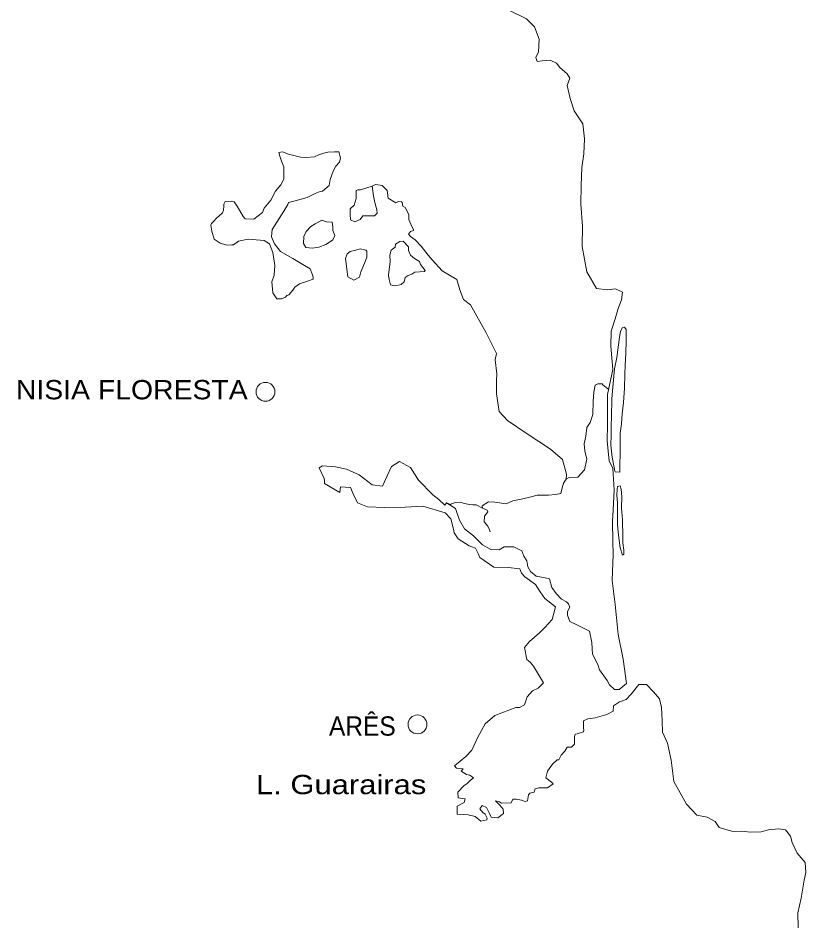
# Model space of a CAD drawing. Extents: x 47169 to 972804, y 7447977 to 9608469.
# Drawn here: x 910858 to 938638, y 9306596 to 9338655 of the extents above; entities that cross this region are included whole.
import ezdxf

# ---------------------------------------------------------------- set-up
doc = ezdxf.new("R2010")
doc.units = 0
doc.header["$LTSCALE"] = 270
doc.layers.add('1', color=7, linetype='Continuous', lineweight=13)
doc.layers.add('2', color=7, linetype='Continuous', lineweight=13)
doc.layers.add('3', color=7, linetype='Continuous')

msp = doc.modelspace()

# ---------------------------------------------------------------- linework, layer by layer
at = {"layer": '1'}
for points in [[(930542.9, 9317264.4), (931011.4, 9317032.8), (931085, 9316622.2), (931096.7, 9316405), (931118.5, 9316210.9), (931296.7, 9315855.1), (931357.4, 9315668.5), (931631.9, 9315287.5), (931709.5, 9315132.9), (931890.1, 9314969.8), (932050.9, 9314967.5), (932317.5, 9315181.7), (932195.2, 9316035.7), (932017.5, 9316906.8), (931914.3, 9317970.2), (931807.4, 9318816.4), (931838.6, 9319741.4), (931829.6, 9320191.3), (931824.9, 9320908.2), (931846.6, 9321301.4), (931873.9, 9322009.2), (931830.6, 9322766.3), (931698.4, 9323041), (931636.8, 9323726.2), (931646.7, 9324321.1), (931642, 9325053.6), (931647.7, 9325374.8), (931837, 9326257.7), (931762, 9327079.3), (931770.3, 9327609.9), (931913.1, 9328042.2), (932015.6, 9328410.4), (932132.1, 9328715.4), (932176.2, 9328987.6), (931930.8, 9329103.5), (931642.1, 9329067.9), (931258.6, 9329112.8), (930915.7, 9329704.7), (930753.5, 9330600), (930756.4, 9331315.8), (930704.3, 9332097.3), (930714.5, 9332748.7), (930733.5, 9333383.5), (930804.6, 9333873.8), (930837.2, 9334395.5), (930773.3, 9334927.8), (930468.2, 9335389.7), (930330.4, 9335826.2), (930226, 9336277.8), (930309.9, 9336534.3), (930216.7, 9336689), (929964.3, 9336916.8), (929845.6, 9337071.7), (929615.5, 9337171.9), (929334.7, 9337150.6), (929158.2, 9337120.8), (929120.3, 9337266.2), (929121.7, 9337298.4), (929203.7, 9337450.7), (929234.8, 9337916.9), (929073.6, 9338344.6), (928781.6, 9338630.3), (928138.2, 9338945.1)], [(927230.2, 9321372.5), (927223, 9321452.3), (927450.2, 9321594.7), (927674.2, 9321583.1), (928072.9, 9321513.8), (928306.7, 9321630.7), (928659.8, 9321691.3), (928900.9, 9321751.6), (929158.7, 9321828.4), (929558, 9321823.3), (929814.3, 9321843.6), (929999.8, 9321882.1), (930042.3, 9322082.4), (930085.6, 9322250.5), (930183.1, 9322386.1), (930202.2, 9322570.9), (930058.3, 9323079.5), (929631.8, 9323447.1), (928808.3, 9323989.3), (928119.7, 9324465.1), (927828, 9324775.2), (927726, 9325395.3), (927732.6, 9325861.7), (927736.6, 9326103.2), (927680.2, 9326594.5), (927731.8, 9326827.9), (927367.6, 9327548.4), (926814.6, 9328545.1), (926561.9, 9328734.1), (926431.2, 9329065.2), (926324, 9329437.2), (925817.1, 9329741), (925454.9, 9330132.5), (925321.9, 9330295.2), (925070.1, 9330611.6), (924857.6, 9330831.4), (924699.8, 9330946.6), (924620.6, 9331035.8), (924694.4, 9331131.7), (924798.9, 9331162), (924799.1, 9331194.1), (924744.5, 9331307.5), (924636.4, 9331550.9), (924631, 9331728.2), (924507.3, 9331970.6), (924427.9, 9332027.7), (924397.7, 9332148.6), (924374.6, 9332173.2), (924270.4, 9332182.8), (924181.3, 9332135.8), (923911.9, 9332308.3), (923868.3, 9332574.5), (923695.4, 9332754.1), (923623.3, 9332762.3), (923463.8, 9332781.2), (923342.5, 9332726.6), (923393.3, 9332387.2), (923437.2, 9332154.3), (923505.2, 9331895.6), (923519.9, 9331774.8), (923430.5, 9331679), (923149.9, 9331675.5), (923013.5, 9331685.3), (922916.1, 9331549.7), (922730.2, 9331463.5), (922579.9, 9331537.6), (922566.8, 9331722.8), (922561.6, 9331924.4), (922707.8, 9332058.6), (922774.9, 9332291.9), (922778.4, 9332476.9), (922779.1, 9332573.2), (922835.8, 9332596.1), (922932.3, 9332603.2), (923342.5, 9332726.6)], [(930183.1, 9322386.1), (930296.7, 9322448.4), (930592.9, 9322460.6), (930828.8, 9322723.7), (930914.7, 9323099.8), (930839.2, 9323390.7), (930819.9, 9323632.4), (930879.5, 9323905.6), (930908.3, 9324210.1), (931031.7, 9324394.3), (931123.5, 9324673.9), (931139.1, 9325140.3), (931160.3, 9325461.5), (931212, 9325710.4), (931301, 9325749.6), (931453, 9325755.2), (931477.1, 9325722.9), (931650.2, 9325576.5), (931686.4, 9325555.6)], [(926814.6, 9311772.7), (926911.7, 9311851.8), (926784.9, 9311950.2), (926665.2, 9311967.7), (926483.2, 9312090.9), (926548.1, 9312170.2), (926316.5, 9312189.6), (926246.2, 9312279.9), (926643.3, 9312603.8), (926854.5, 9312826.1), (927070.8, 9313289.9), (927325.9, 9313761.1), (927675.1, 9314054.4), (928415.7, 9314333.8), (928535.5, 9314339.6), (928721.3, 9314433.5), (928805.4, 9314706.5), (928993.2, 9314921.2), (929202.4, 9315015), (929381.2, 9315205.4), (929038.5, 9315797.3), (928920.8, 9315935.6), (928793.9, 9316025.1), (928720.5, 9316453.4), (928892.8, 9316659.3), (929241.1, 9316969.2), (929436.5, 9317151.7), (929689.1, 9317436.8), (929807.8, 9317885.8), (929436.2, 9318181.1), (929263.8, 9318416.1), (929100.4, 9318676.6), (928728.6, 9318938.5), (928610.9, 9319076.8), (928556.5, 9319222.3), (928141, 9319268.5), (927637.6, 9319283.2), (927138.9, 9319628.1), (927076.6, 9319765.9), (926991.5, 9319951.6), (926769.2, 9320042.9), (926372.8, 9320281.8), (926232.4, 9320493.3), (926210, 9320622), (926119.5, 9320992.7), (925922.5, 9321196.9), (925126.8, 9321433), (924510, 9321400.9), (923773.5, 9321386.2), (923173.8, 9321410.4), (922831, 9321560.2), (922668.1, 9321876), (922584.2, 9322094.9), (922231.8, 9322122.9), (922197.1, 9321922.6), (921665.9, 9322235.4), (921660.1, 9322356.2), (921645, 9322412.9), (921474.6, 9322785.2), (921587.2, 9322864.2), (922051.6, 9322825.4), (922442.4, 9322739.6), (922886.8, 9322540.3), (923345.6, 9322189.2), (923704.6, 9322143.4), (923870.2, 9322503.4), (924020.1, 9322839.1), (924303, 9323012.2), (924699.7, 9322805.5), (924980.3, 9322351.4), (925484.6, 9321838.2), (925690.8, 9321674.9), (925911.2, 9321478.4), (925968.3, 9321550), (926285.2, 9321352.7), (926423.1, 9320948.4), (926595, 9320640.3), (926918.2, 9320395.3), (927234.1, 9320077.2), (927526.8, 9319904.5), (927822.8, 9319892.4), (928001, 9320001.9), (928344.8, 9319997.2), (928623.3, 9319865.6), (928691.8, 9319671.2), (928793.7, 9319508.7), (928829.8, 9319291.2), (928924.1, 9319136.5), (929121.4, 9318973.3), (929448.1, 9318904.5), (929592, 9318870.2), (929683, 9318571.5), (929831.1, 9318352.1), (930020.4, 9318156.9), (930195, 9318065.8), (930265.4, 9317992.2), (930312.3, 9317878.8), (930230.2, 9317719.9), (930228.1, 9317591.4), (930311.9, 9317372.5), (930542.9, 9317264.4)], [(925968.3, 9321550), (926104.3, 9321500.2), (926136.7, 9321523.3), (926281.1, 9321562.1), (926457.5, 9321575.3), (926592.5, 9321533.3), (926784.1, 9321490.9), (926888.3, 9321489.1), (927015.8, 9321479.3), (927230.2, 9321372.5), (927397.1, 9321297.1), (927427.7, 9321232.6), (927305.8, 9321089.4), (927294.3, 9320880.1), (927419.6, 9320726.3), (927481.9, 9320605.1), (927504.7, 9320531.8)], [(938478.9, 9307606.4), (938584.6, 9308240.6), (938637.7, 9308513.9), (938619.3, 9308867.5), (938336.7, 9309193.2), (938158.8, 9309573.5), (938098.4, 9309800), (937924.8, 9310011.9), (937677.8, 9310055.8), (937317.2, 9310019.8), (937068.2, 9309950.7), (936683.3, 9309932.5), (936379.8, 9309969.2), (936068.1, 9309964.8), (935582.3, 9310100.3), (935440.8, 9310311.9), (935163.6, 9310460.2), (934788.2, 9310529.5), (934426.3, 9310921.1), (933983.1, 9311723.3), (933891.1, 9312473.1), (933764.7, 9313077.9), (933586.8, 9313458.2), (933569.8, 9313860.5), (933545.6, 9314336), (933477.9, 9314634.6), (933265.8, 9314886.6), (933021.4, 9315139.9), (932949.3, 9315140.4), (932749.8, 9315143), (932472.3, 9314809.3), (932301.2, 9314617.8), (932067.7, 9314533.1), (931857.1, 9314390.6), (931838, 9314206.8), (931620.8, 9314088.7), (931210.8, 9313973.2), (930945.5, 9313937.4), (930800.8, 9313858.7), (930798.9, 9313753.5), (930796.7, 9313600.6), (930802.8, 9313528.5), (930802.4, 9313472), (930569, 9313402.8), (930504.6, 9313387.8), (930479.5, 9313299.3), (930477.8, 9313211.8), (930475.8, 9313091), (930475.4, 9313034.5), (930369.3, 9312938.9), (930217.3, 9312933.4), (930143.2, 9312797.7), (930013.4, 9312646.8), (929922.4, 9312486.8), (929865.9, 9312487.2), (929704, 9312336.6), (929531.4, 9312081.9), (929472.1, 9311857.4), (929669.4, 9311702), (929724.4, 9311637.3), (929530.4, 9311494.7), (929218.8, 9311499.2), (929090, 9311468), (929055.8, 9311348.6), (928903.6, 9311309.8), (928854.4, 9311254.8), (928819.6, 9311045.6), (928738.5, 9311023), (928611.3, 9311064.9), (928419.7, 9311099.5), (928300, 9311101.5), (928250.2, 9310965.6), (927905.3, 9310961.5), (927834.7, 9311010.7), (927698.6, 9311045), (927840.5, 9310882.2), (927965.8, 9310743.9), (927971.4, 9310590.9), (927769.6, 9310440.6), (927538, 9310460), (927475.8, 9310597.9), (927375.3, 9310808), (927223.9, 9310874.5), (927142.1, 9310763.2), (927244.3, 9310632.8), (927323.7, 9310568), (927393.6, 9310430.1), (927392, 9310365.8), (927175.6, 9310328.6), (926970.4, 9310484.1), (926730.3, 9310543.5), (926555.2, 9310553.6), (926339.1, 9310573), (926343.3, 9310854.3), (926586, 9310987.7), (926627.9, 9311108.2), (926379.9, 9311151), (926366.9, 9311345), (926571.4, 9311567.3), (926692.9, 9311654), (926814.6, 9311772.7)], [(938365.6, 9306554.6), (938350.8, 9307085.5), (938478.9, 9307606.4)]]:
    msp.add_lwpolyline(points, dxfattribs=at)
for points in [[(919536.1, 9331956.6), (919764.2, 9332235.3), (919929.5, 9332554.4), (920117.3, 9332769.1), (920231.9, 9332968.8), (920231.6, 9333410.9), (920146.4, 9333605.3), (920084.5, 9333783), (920055.4, 9333911.7), (920183.1, 9333934.1), (920397.7, 9333851.8), (920813, 9333749.2), (921020.3, 9333738.8), (921308.9, 9333766.8), (921462.4, 9333837.7), (921639.2, 9333890.8), (921775.8, 9333921.9), (922008.9, 9333942.5), (922168.6, 9333940.2), (922229.2, 9333722.7), (922187.1, 9333577.8), (922064.1, 9333434.7), (921965.2, 9333251.4), (921856.7, 9332963), (921829.7, 9332746.1), (921594.3, 9332556), (921514.4, 9332541.1), (921328.6, 9332463.7), (921047, 9332322.8), (920629.2, 9332214.9), (920395.9, 9332154.5), (920371, 9332081.6), (920230.7, 9331842.1), (919812.5, 9331196.9), (919792.9, 9330940), (919901, 9330688.9), (920113.2, 9330420.4), (920540.7, 9330173.7), (920898.5, 9329959.6), (921160.3, 9329811.5), (921244.3, 9329601.5), (921267, 9329520.5), (921266.5, 9329448.5), (921057.5, 9329377.9), (920775.1, 9329285.7), (920621.2, 9329159.4), (920547.3, 9329063.5), (920409.7, 9328896.1), (920328.6, 9328865.7), (920288.2, 9328809.4), (920150.3, 9328747.2), (919975.1, 9328749.6), (919842.4, 9328967.7), (919799.6, 9329346.8), (919883.3, 9329586.7), (919904.6, 9329932.2), (919840.1, 9330392.4), (919716.9, 9330691.3), (919534.7, 9330806.7), (918974.9, 9330853.8), (918629.5, 9330786.4), (918451.2, 9330660.2), (918387.9, 9330652.9), (918211.6, 9330646.4), (917980.2, 9330714.5), (917766.1, 9330862.2), (917682.6, 9331136.4), (917654.1, 9331346), (917678.9, 9331410.1), (917752.8, 9331497.1), (917842.1, 9331585.1), (918068.6, 9331782.9), (918102.5, 9331879.1), (918112.4, 9332023), (918114, 9332088.4), (918163.4, 9332183.3), (918379.8, 9332197.3), (918475.1, 9332180), (918584.8, 9332017.5), (918787.6, 9331660.5), (918858, 9331579.1), (919170.7, 9331567), (919469.6, 9331804.2)], [(921737.6, 9331468.2), (921929.4, 9331458), (921959.3, 9331297.1), (921957.2, 9331159.8), (922027, 9330989.8), (921951.7, 9330838.5), (921797.8, 9330727.7), (921709.8, 9330665.2), (921467.3, 9330571.6), (921235.3, 9330534.4), (921003.7, 9330561.5), (920918.2, 9330707.3), (920929.9, 9330956.5), (921019.8, 9331132), (921183, 9331299.2), (921329, 9331401.3), (921570.5, 9331527)], [(923972.7, 9330070.9), (923968.7, 9330288.1), (924011, 9330472.8), (924149.2, 9330576), (924166.6, 9330680), (924320.3, 9330774.2), (924440.2, 9330788.9), (924629.6, 9330585.9), (924619.8, 9330457.5), (924697.4, 9330295.2), (924839.7, 9330180), (925014.2, 9330073.6), (925052.2, 9329968), (925217.1, 9329748.6), (925192.4, 9329717.8), (924847.4, 9329698), (924742.6, 9329626.8), (924613.6, 9329580), (924501.1, 9329508.8), (924474.4, 9329348.3), (924368.4, 9329253.8), (924167.3, 9329207.6), (923992.3, 9329243.2), (923947.1, 9329436.3), (923917.1, 9329589.4)], [(922943, 9329699.3), (922891.8, 9329514.6), (922698.1, 9329412.9), (922483.7, 9329528.6), (922398.5, 9330180.6), (922465, 9330340.8), (922562.1, 9330419.9), (922763.2, 9330473.9), (922923.2, 9330511.5), (923122.6, 9330469.1), (923154.5, 9330436.8), (923150.8, 9330227.4), (923108.8, 9330091.4)], [(932090.4, 9324017.6), (932084.2, 9323623.2), (932087.6, 9323334), (932079.7, 9322858.7), (932077.7, 9322730.2), (932075.9, 9322633.8), (931908.5, 9322643.9), (931900.9, 9322676.1), (931804.7, 9323168.7), (931763.4, 9323587.9), (931769.3, 9323941.3), (931773.9, 9324279.2), (931787.3, 9324592.7), (931797.4, 9325228.6), (931828.1, 9325638.3), (931893.8, 9326280.5), (931972.1, 9326682.2), (932071.6, 9327405), (932098.6, 9327605.4), (932157.1, 9327724.6), (932237.2, 9327756.2), (932299.8, 9327674.8), (932301.3, 9327264.8), (932287.1, 9326830.6), (932264, 9326404.2), (932250.7, 9326090.7), (932243.8, 9325599.9), (932203.5, 9325093.8), (932165.1, 9324691.9), (932134.8, 9324338.6)], [(932170.2, 9320958.9), (932166.7, 9320790.5), (932186.9, 9320516.7), (932188.6, 9320138.8), (932216.7, 9319880.4), (932222.3, 9319744.1), (932174.4, 9319712.3), (932089.8, 9319971.1), (932039.1, 9320317.2), (932012.5, 9320632.1), (931999.5, 9320817.2), (931990.2, 9321219.5), (931994.9, 9321557.4), (931975.7, 9321822.3), (931978.3, 9322031.8), (931995.7, 9322128), (932092.3, 9322150.6), (932130.3, 9322038.4), (932150.6, 9321772.3), (932136.6, 9321378)]]:
    msp.add_lwpolyline(points, close=True, dxfattribs=at)
at = {"layer": '2'}
for centre, radius in [((919579.5, 9325473), 332.3), ((924940.6, 9313737.5), 333)]:
    msp.add_circle(centre, radius, dxfattribs=at)

# ---------------------------------------------------------------- texts
at = {"layer": '3'}
for s, height, width, p in [('NISIA FLORESTA', 680.6, 1.1, (910775.9, 9325206.8)), ('ARÊS', 680.6, 0.95, (921819.3, 9313339.5)), ('L. Guarairas', 680.5, 1.2, (919244.9, 9311275.7))]:
    msp.add_text(s, height=height, dxfattribs=dict(at, width=width)).set_placement(p)

doc.saveas('drawing.dxf')
